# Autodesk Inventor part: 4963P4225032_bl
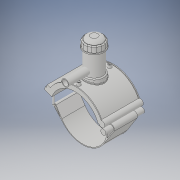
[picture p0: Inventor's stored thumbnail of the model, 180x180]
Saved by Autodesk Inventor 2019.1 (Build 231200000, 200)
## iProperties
Created: 2017-07
Part Number: 4963P4225032_bl
Material: Generic
Document SubType Name: Modeling
Designer: KIM
Density: 1 g/cm^3
Appearance: Default
Author: KIM
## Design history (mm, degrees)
derived "4963P4.ipt"
feature "Solid1::4963P4.ipt" dims "ScaleForDerivedMember" = 10
feature "Solid2::4963P4.ipt" dims "ScaleForDerivedMember" = 10
feature "Solid3::4963P4.ipt" dims "ScaleForDerivedMember" = 10
tag "TaggingFeature1"
body "Solid1"
body "Solid2"
body "Solid3"
other parameters: "d0" = 225 [user parameter], "d2" = 295.1 [user parameter], "d3" = 56.25 [user parameter], "d4" = 176 [user parameter], "d5" = 0 [user parameter], "d6" = 0.1 [user parameter], "d8" = 0 [user parameter], "d19" = 6 [user parameter], "d20" = 6 [user parameter], "d21" = 105.6 [user parameter], "d23" = 0 [user parameter], "d24" = 52.8 [user parameter], "d26" = 0 [user parameter], "d27" = 3 [user parameter], "d28" = 3 [user parameter], "d29" = 3 [user parameter], "d30" = 75 [user parameter], "d31" = 6 [user parameter], "d32" = 0 [user parameter], "d33" = 0 [user parameter], "d34" = 0.6 [user parameter], "d40" = 135.72 [user parameter], "d43" = 0 [user parameter], "d45" = 0 [user parameter], "d47" = 236.1 [user parameter], "d70" = 15 [user parameter], "d72" = 0 [user parameter], "d73" = 6 [user parameter], "d75" = 5 [user parameter], "d76" = 0 [user parameter], "d77" = 11.25 [user parameter], "d78" = 142.5 [user parameter], "d79" = 15 [user parameter], "d80" = 70.4 [user parameter], "d82" = 5 deg [user parameter], "d84" = 4 [user parameter], "d85" = 14 [user parameter], "d86" = 0 [user parameter], "d87" = 3 [user parameter], "d88" = 0 [user parameter], "d89" = 1 [user parameter], "d90" = 1 [user parameter], "d91" = 140.8 [user parameter], "d92" = 0 [user parameter], "d93" = 0.5 [user parameter], "d94" = 118.42105 [user parameter], "d96" = 266.22 [user parameter], "d97" = 3.52 [user parameter], "d98" = 0 [user parameter], "d102" = 2.25 [user parameter], "d120" = 140 deg [user parameter], "d121" = 24.228 [user parameter], "d122" = 20 deg [user parameter], "d123" = 522 [user parameter], "d124" = 156.6 [user parameter], "d126" = 0 [user parameter], "d143" = 231.75 [user parameter], "d145" = 27.69231 [user parameter], "d149" = 3.375 [user parameter], "d150" = 30.46154 [user parameter], "d153" = 176 [user parameter], "d154" = 0 [user parameter], "d156" = 130.5 [user parameter], "d157" = 160 deg [user parameter], "d159" = 7.2 [user parameter], "d161" = 3.375 [user parameter], "d162" = 105.6 [user parameter], "d163" = 0 [user parameter], "d164" = 112.5 [user parameter], "d167" = 22.5 [user parameter], "d168" = 127.31707 [user parameter], "d170" = 3.375 [user parameter], "d172" = 0 [user parameter], "d173" = 1 [user parameter], "d175" = 112.5 [user parameter], "d176" = 20 deg [user parameter], "d177" = 15.75 [user parameter], "d178" = 36 [user parameter], "d180" = 0 [user parameter], "d183" = 14.4 [user parameter], "d184" = 12.6 [user parameter], "d185" = 57.2 [user parameter], "d186" = 57.2 [user parameter], "d187" = 130.5 [user parameter], "d188" = 10.8 [user parameter], "d189" = 15.75 [user parameter], "d190" = 0 [user parameter], "d191" = 195.75 [user parameter], "d193" = 7.2 [user parameter], "d194" = 6.16 [user parameter], "d195" = 90 deg [user parameter], "d197" = 0 [user parameter], "d199" = 0 [user parameter], "d200" = 18 [user parameter], "d202" = 0 [user parameter], "d203" = 177 [user parameter], "d204" = 85.5 [user parameter], "d205" = 63 [user parameter], "d206" = 76.5 [user parameter], "d207" = 132.75 [user parameter], "d208" = 138.06 [user parameter], "d209" = 164.61 [user parameter], "d210" = 77.4 [user parameter], "d212" = 72 [user parameter], "d213" = 36 [user parameter], "d216" = 0 [user parameter], "d217" = 22.5 [user parameter], "d218" = 22.5 [user parameter], "d219" = 4.5 [user parameter], "d222" = 225 [user parameter], "d224" = 0 [user parameter], "d225" = 56 [user parameter], "d226" = 32 [user parameter], "d227" = 25.6 [user parameter], "d228" = 132 [user parameter], "d230" = 4.5 [user parameter], "d_" = 225 [user parameter], "B_" = 227 [user parameter], "L_" = 176 [user parameter], "d_t" = 6 [user parameter]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
